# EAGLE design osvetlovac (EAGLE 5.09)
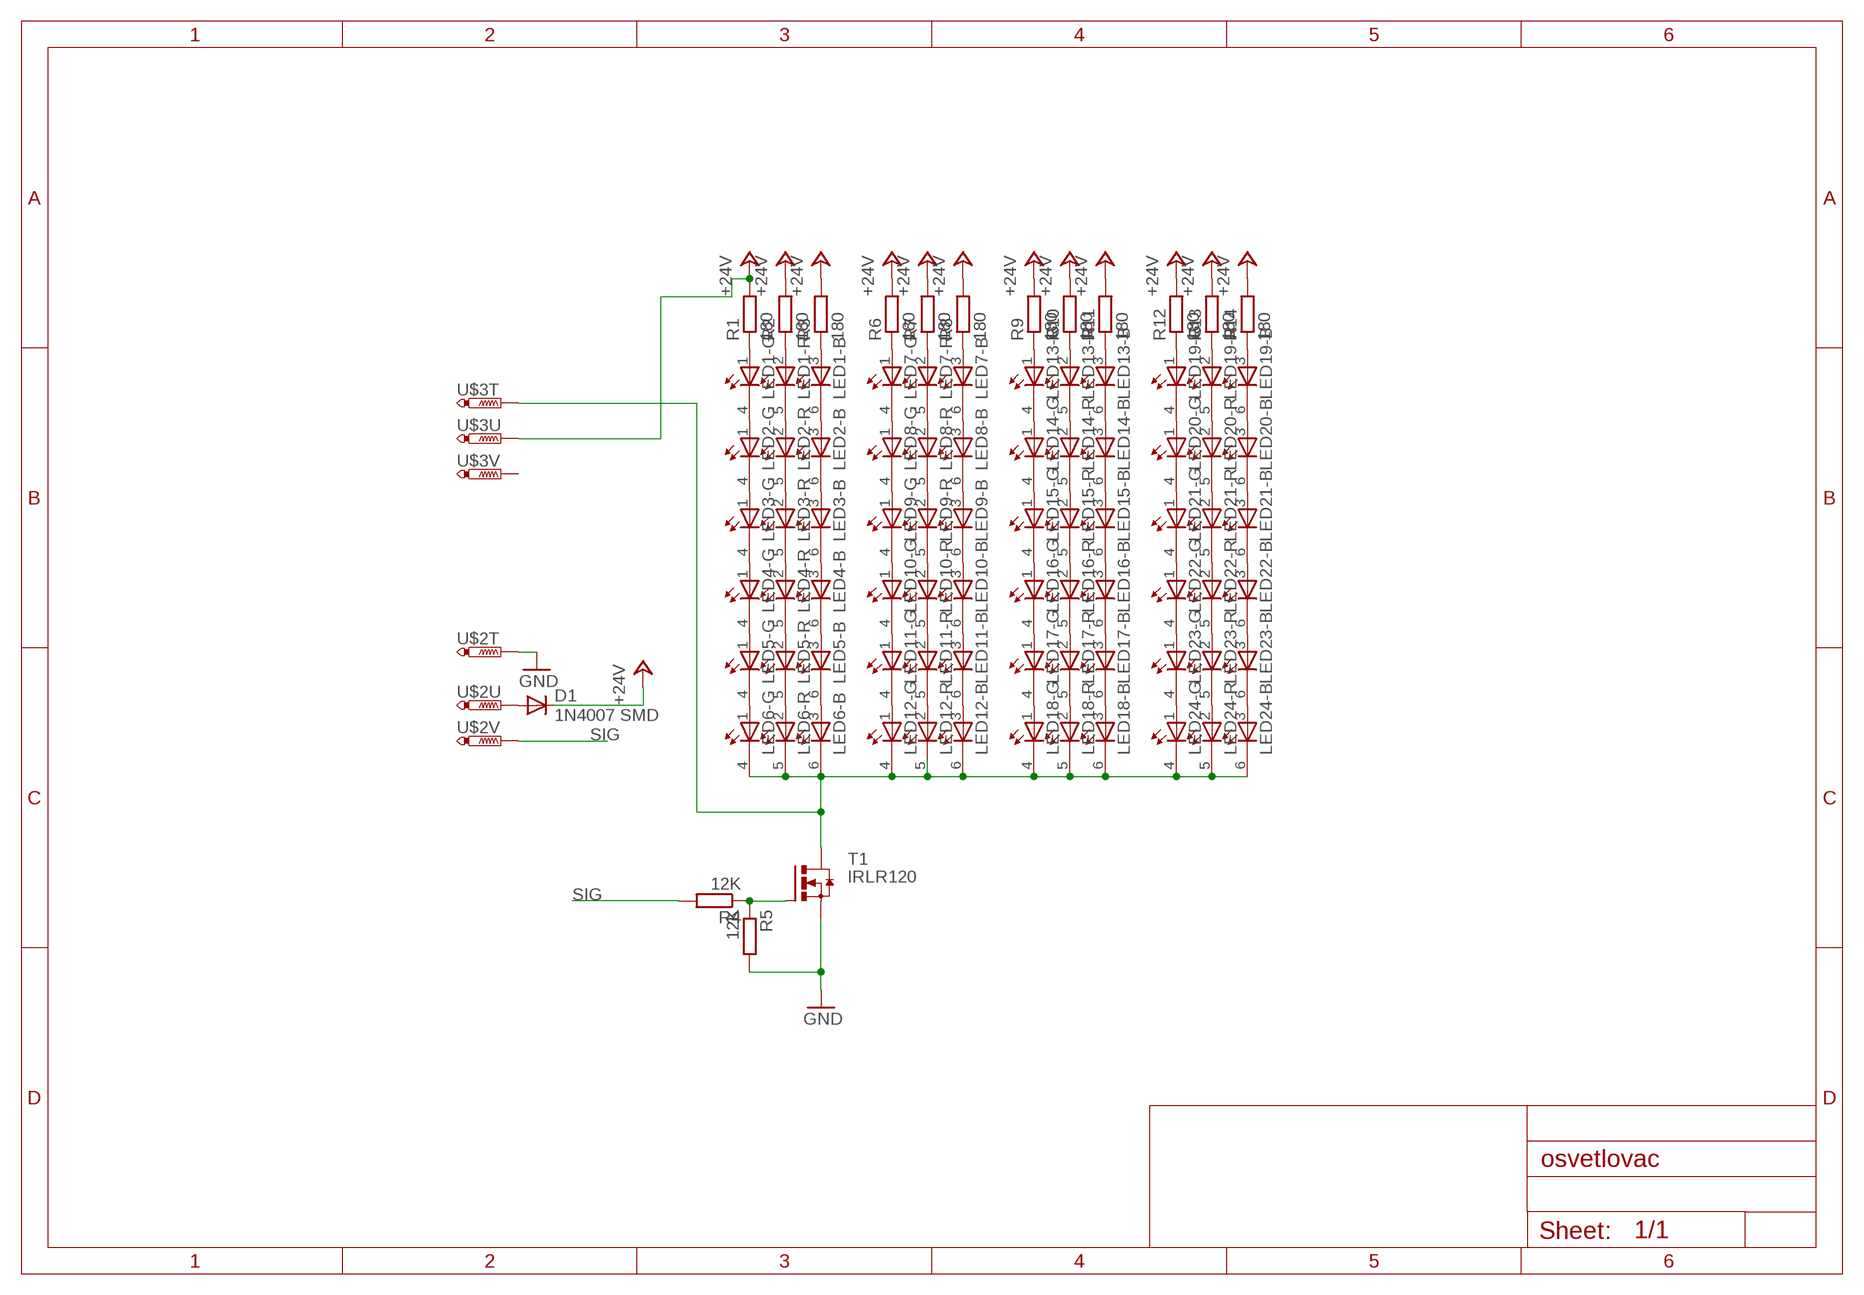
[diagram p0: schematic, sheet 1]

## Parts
D1  1N4007 SMD  DIODE-MELF-MLL41  [MELF-MLL41]
LED1  OVSTRGBBCR8  [OVSTRGBBCR8]
LED2  OVSTRGBBCR8  [OVSTRGBBCR8]
LED3  OVSTRGBBCR8  [OVSTRGBBCR8]
LED4  OVSTRGBBCR8  [OVSTRGBBCR8]
LED5  OVSTRGBBCR8  [OVSTRGBBCR8]
LED6  OVSTRGBBCR8  [OVSTRGBBCR8]
LED7  OVSTRGBBCR8  [OVSTRGBBCR8]
LED8  OVSTRGBBCR8  [OVSTRGBBCR8]
LED9  OVSTRGBBCR8  [OVSTRGBBCR8]
LED10  OVSTRGBBCR8  [OVSTRGBBCR8]
LED11  OVSTRGBBCR8  [OVSTRGBBCR8]
LED12  OVSTRGBBCR8  [OVSTRGBBCR8]
LED13  OVSTRGBBCR8  [OVSTRGBBCR8]
LED14  OVSTRGBBCR8  [OVSTRGBBCR8]
LED15  OVSTRGBBCR8  [OVSTRGBBCR8]
LED16  OVSTRGBBCR8  [OVSTRGBBCR8]
LED17  OVSTRGBBCR8  [OVSTRGBBCR8]
LED18  OVSTRGBBCR8  [OVSTRGBBCR8]
LED19  OVSTRGBBCR8  [OVSTRGBBCR8]
LED20  OVSTRGBBCR8  [OVSTRGBBCR8]
LED21  OVSTRGBBCR8  [OVSTRGBBCR8]
LED22  OVSTRGBBCR8  [OVSTRGBBCR8]
LED23  OVSTRGBBCR8  [OVSTRGBBCR8]
LED24  OVSTRGBBCR8  [OVSTRGBBCR8]
R1  180  R-EU_R0805  [R0805]
R2  180  R-EU_R0805  [R0805]
R3  180  R-EU_R0805  [R0805]
R4  12K  R-EU_R0805  [R0805]
R5  12K  R-EU_R0805  [R0805]
R6  180  R-EU_R0805  [R0805]
R7  180  R-EU_R0805  [R0805]
R8  180  R-EU_R0805  [R0805]
R9  180  R-EU_R0805  [R0805]
R10  180  R-EU_R0805  [R0805]
R11  180  R-EU_R0805  [R0805]
R12  180  R-EU_R0805  [R0805]
R13  180  R-EU_R0805  [R0805]
R14  180  R-EU_R0805  [R0805]
T1  IRLR120  [D-PAK_TO252AA]
U$2  3PIN  [PIN3]
U$3  3PIN  [PIN3]

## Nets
+24V: D1.C R1.2 R2.2 R3.2 R6.2 R7.2 R8.2 R9.2 R10.2 R11.2 R12.2 R13.2 R14.2 U$3.2
GND: R5.2 T1.3(S) U$2.1
N$1: LED1.4(-G:C) LED2.1(-G:A)
N$2: LED1.5(-R:C) LED2.2(-R:A)
N$3: LED1.6(-B:C) LED2.3(-B:A)
N$4: LED2.4(-G:C) LED3.1(-G:A)
N$5: LED2.5(-R:C) LED3.2(-R:A)
N$6: LED2.6(-B:C) LED3.3(-B:A)
N$7: LED3.4(-G:C) LED4.1(-G:A)
N$8: LED3.5(-R:C) LED4.2(-R:A)
N$9: LED3.6(-B:C) LED4.3(-B:A)
N$10: LED4.4(-G:C) LED5.1(-G:A)
N$11: LED4.5(-R:C) LED5.2(-R:A)
N$12: LED4.6(-B:C) LED5.3(-B:A)
N$13: LED5.4(-G:C) LED6.1(-G:A)
N$14: LED5.5(-R:C) LED6.2(-R:A)
N$15: LED5.6(-B:C) LED6.3(-B:A)
N$16: LED1.1(-G:A) R1.1
N$17: LED1.2(-R:A) R2.1
N$18: LED1.3(-B:A) R3.1
N$19: R4.1 R5.1 T1.1(G)
N$20: LED7.4(-G:C) LED8.1(-G:A)
N$21: LED7.5(-R:C) LED8.2(-R:A)
N$22: LED7.6(-B:C) LED8.3(-B:A)
N$23: LED8.4(-G:C) LED9.1(-G:A)
N$24: LED8.5(-R:C) LED9.2(-R:A)
N$25: LED8.6(-B:C) LED9.3(-B:A)
N$26: LED9.4(-G:C) LED10.1(-G:A)
N$27: LED9.5(-R:C) LED10.2(-R:A)
N$28: LED9.6(-B:C) LED10.3(-B:A)
N$29: LED10.4(-G:C) LED11.1(-G:A)
N$30: LED10.5(-R:C) LED11.2(-R:A)
N$31: LED10.6(-B:C) LED11.3(-B:A)
N$32: LED11.4(-G:C) LED12.1(-G:A)
N$33: LED11.5(-R:C) LED12.2(-R:A)
N$34: LED11.6(-B:C) LED12.3(-B:A)
N$35: LED7.1(-G:A) R6.1
N$36: LED7.2(-R:A) R7.1
N$37: LED7.3(-B:A) R8.1
N$38: LED13.4(-G:C) LED14.1(-G:A)
N$39: LED13.5(-R:C) LED14.2(-R:A)
N$40: LED13.6(-B:C) LED14.3(-B:A)
N$41: LED14.4(-G:C) LED15.1(-G:A)
N$42: LED14.5(-R:C) LED15.2(-R:A)
N$43: LED14.6(-B:C) LED15.3(-B:A)
N$44: LED15.4(-G:C) LED16.1(-G:A)
N$45: LED15.5(-R:C) LED16.2(-R:A)
N$46: LED15.6(-B:C) LED16.3(-B:A)
N$47: LED16.4(-G:C) LED17.1(-G:A)
N$48: LED16.5(-R:C) LED17.2(-R:A)
N$49: LED16.6(-B:C) LED17.3(-B:A)
N$50: LED17.4(-G:C) LED18.1(-G:A)
N$51: LED17.5(-R:C) LED18.2(-R:A)
N$52: LED17.6(-B:C) LED18.3(-B:A)
N$53: LED13.1(-G:A) R9.1
N$54: LED13.2(-R:A) R10.1
N$55: LED13.3(-B:A) R11.1
N$56: LED19.4(-G:C) LED20.1(-G:A)
N$57: LED19.5(-R:C) LED20.2(-R:A)
N$58: LED19.6(-B:C) LED20.3(-B:A)
N$59: LED20.4(-G:C) LED21.1(-G:A)
N$60: LED20.5(-R:C) LED21.2(-R:A)
N$61: LED20.6(-B:C) LED21.3(-B:A)
N$62: LED21.4(-G:C) LED22.1(-G:A)
N$63: LED21.5(-R:C) LED22.2(-R:A)
N$64: LED21.6(-B:C) LED22.3(-B:A)
N$65: LED22.4(-G:C) LED23.1(-G:A)
N$66: LED22.5(-R:C) LED23.2(-R:A)
N$67: LED22.6(-B:C) LED23.3(-B:A)
N$68: LED23.4(-G:C) LED24.1(-G:A)
N$69: LED23.5(-R:C) LED24.2(-R:A)
N$70: LED23.6(-B:C) LED24.3(-B:A)
N$71: LED19.1(-G:A) R12.1
N$72: LED19.2(-R:A) R13.1
N$73: LED19.3(-B:A) R14.1
N$74: LED6.4(-G:C) LED6.5(-R:C) LED6.6(-B:C) LED12.4(-G:C) LED12.5@1(-R:C) LED12.6(-B:C) LED18.4(-G:C) LED18.5(-R:C) LED18.6(-B:C) LED24.4(-G:C) LED24.5(-R:C) LED24.6(-B:C) T1.4(D) U$3.1
N$75: D1.A U$2.2
SIG: R4.2 U$2.3
Unconnected: LED1.4@1(-G:C) LED1.5@1(-R:C) LED1.6@1(-B:C) LED2.4@1(-G:C) LED2.5@1(-R:C) LED2.6@1(-B:C) LED3.4@1(-G:C) LED3.5@1(-R:C) LED3.6@1(-B:C) LED4.4@1(-G:C) LED4.5@1(-R:C) LED4.6@1(-B:C) LED5.4@1(-G:C) LED5.5@1(-R:C) LED5.6@1(-B:C) LED6.4@1(-G:C) LED6.5@1(-R:C) LED6.6@1(-B:C) LED7.4@1(-G:C) LED7.5@1(-R:C) LED7.6@1(-B:C) LED8.4@1(-G:C) LED8.5@1(-R:C) LED8.6@1(-B:C) LED9.4@1(-G:C) LED9.5@1(-R:C) LED9.6@1(-B:C) LED10.4@1(-G:C) LED10.5@1(-R:C) LED10.6@1(-B:C) LED11.4@1(-G:C) LED11.5@1(-R:C) LED11.6@1(-B:C) LED12.4@1(-G:C) LED12.5(-R:C) LED12.6@1(-B:C) LED13.4@1(-G:C) LED13.5@1(-R:C) LED13.6@1(-B:C) LED14.4@1(-G:C) LED14.5@1(-R:C) LED14.6@1(-B:C) LED15.4@1(-G:C) LED15.5@1(-R:C) LED15.6@1(-B:C) LED16.4@1(-G:C) LED16.5@1(-R:C) LED16.6@1(-B:C) LED17.4@1(-G:C) LED17.5@1(-R:C) LED17.6@1(-B:C) LED18.4@1(-G:C) LED18.5@1(-R:C) LED18.6@1(-B:C) LED19.4@1(-G:C) LED19.5@1(-R:C) LED19.6@1(-B:C) LED20.4@1(-G:C) LED20.5@1(-R:C) LED20.6@1(-B:C) LED21.4@1(-G:C) LED21.5@1(-R:C) LED21.6@1(-B:C) LED22.4@1(-G:C) LED22.5@1(-R:C) LED22.6@1(-B:C) LED23.4@1(-G:C) LED23.5@1(-R:C) LED23.6@1(-B:C) LED24.4@1(-G:C) LED24.5@1(-R:C) LED24.6@1(-B:C) U$3.3

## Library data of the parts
D1 = diode:DIODE-: DIODE
LED1-LED24 = led:OVSTRGBBCR8: Full Color PLCC6 LED OVSTRGBBCR8 Source: www.optekinc.com .. ovstrgbbcr8.pdf
R1-R14 = rcl:R-EU_: RESISTOR, European symbol
T1 = transistor-power:IRLR120
U$2 U$3 = testpad:3PIN

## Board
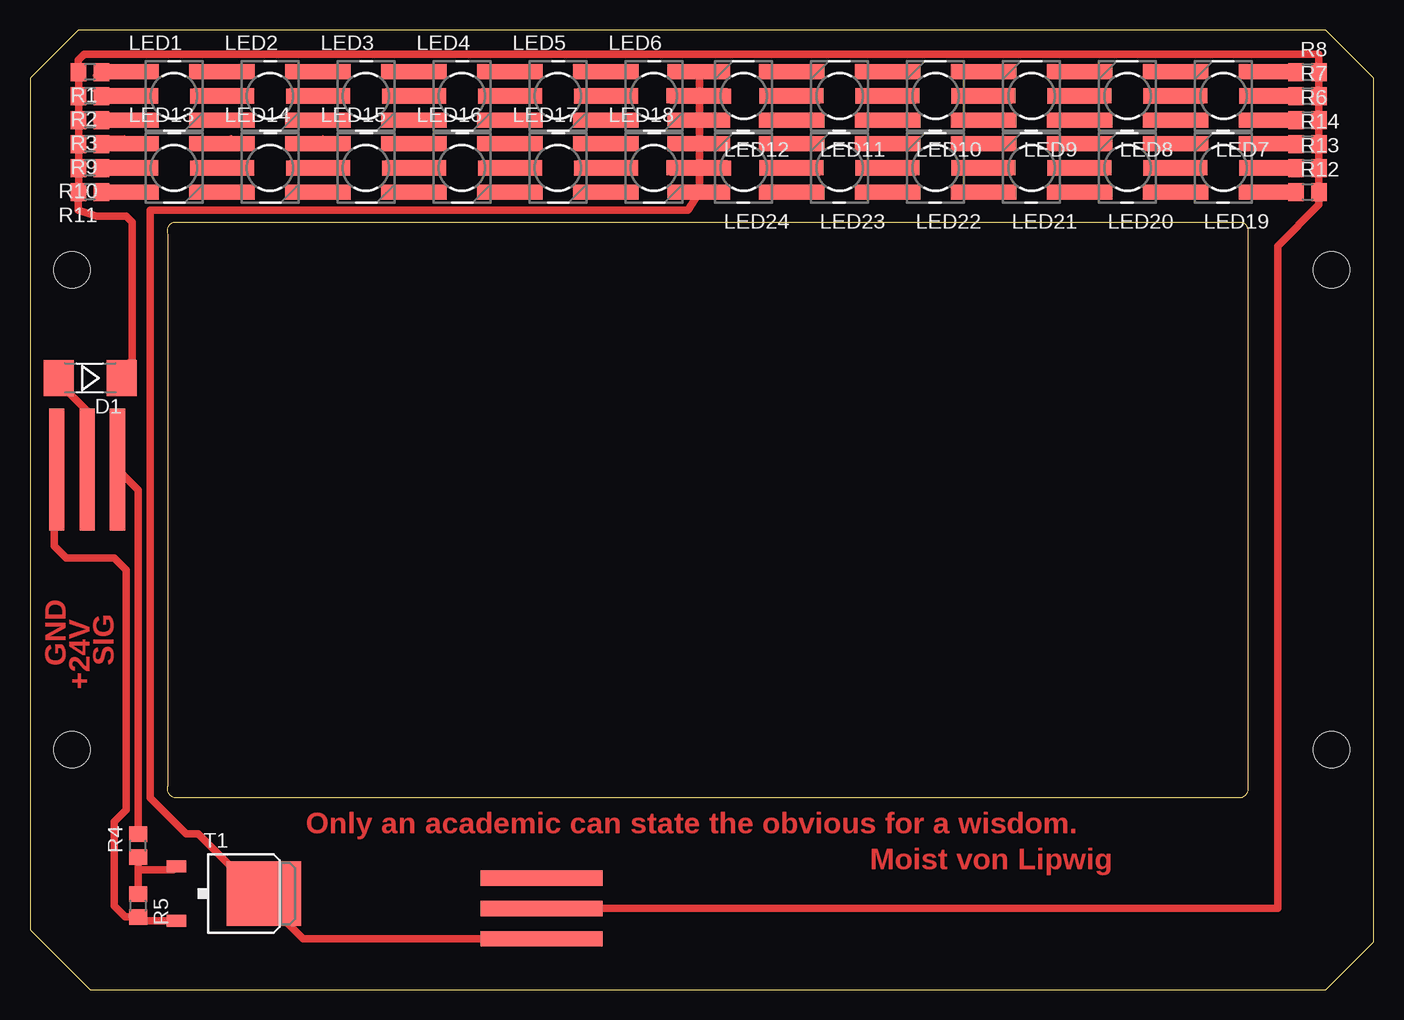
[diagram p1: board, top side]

Size 112 x 80 mm. Coordinates in mm from the lower left corner, seen from the top.
Outline: 108,0 112,4 112,76 108,80 4,80 0,76 0,5 5,0 108,0
Outline: 11.5,63 arc-90 12,64 101,64 arc-90 101.5,63 101.5,17 arc-90 101,16 12,16 arc-90 11.5,17 11.5,63
Copper layers (1*16): Top 0.035mm / dielectric 1.5mm / Bottom 0.035mm
Design rules "default": minimum track width 10mil, minimum drill 24mil, track to track 8mil, track to pad 8mil, pad to pad 8mil, via to via 8mil, smd to smd 8mil, copper to edge 40mil, drill to drill 8mil, minimum pad ring 10mil, minimum via ring 8mil, stop-mask expansion 4mil, vias tented up to drill 0mil, thermal gap 10mil
Holes 3 mm at 3.5,60 3.5,20 108.5,60 108.5,20

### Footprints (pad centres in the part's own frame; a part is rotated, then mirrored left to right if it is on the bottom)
MELF-MLL41 = smd 2.5 x 3: A 2.625,0; C -2.625,0
OVSTRGBBCR8 = smd 5.08 x 1.27: 1 -3.802,2.026; 2 -3.833,0; 3 -3.802,-2.026; 4 3.812,2.026; 5@1 3.91,-0.025; 6 3.812,-2.026 | smd 1.676 x 0.813: 4@1 3.322,1.936 | smd 1.422 x 0.711: 5 3.692,0 | smd 0.305 x 0.152: 6@1 3.002,-1.936
R0805 = smd 1.3 x 1.5: 1 -0.95,0; 2 0.95,0
D-PAK_TO252AA = smd 1 x 1.6: 1 -2.28,-4.8; 3 2.28,-4.8 | smd 5.4 x 6.2: 4 0,2.5
PIN3 = smd 1.27 x 10.16: 1 -17.78,6.35; 2 -15.24,6.35; 3 -12.7,6.35

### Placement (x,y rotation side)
D1  5,51 180 top
LED1  12,74.5 0 top
LED2  20,74.5 0 top
LED3  28,74.5 0 top
LED4  36,74.5 0 top
LED5  44,74.5 0 top
LED6  52,74.5 0 top
LED7  99.5,74.5 180 top
LED8  91.5,74.5 180 top
LED9  83.5,74.5 180 top
LED10  75.5,74.5 180 top
LED11  67.5,74.5 180 top
LED12  59.5,74.5 180 top
LED13  12,68.5 0 top
LED14  20,68.5 0 top
LED15  28,68.5 0 top
LED16  36,68.5 0 top
LED17  44,68.5 0 top
LED18  52,68.5 0 top
LED19  99.5,68.5 180 top
LED20  91.5,68.5 180 top
LED21  83.5,68.5 180 top
LED22  75.5,68.5 180 top
LED23  67.5,68.5 180 top
LED24  59.5,68.5 180 top
R1  5,76.5 180 top
R2  5,74.5 180 top
R3  5,72.5 180 top
R4  9,12 90 top
R5  9,7 270 top
R6  106.5,72.5 0 top
R7  106.5,74.5 0 top
R8  106.5,76.5 0 top
R9  5,70.5 180 top
R10  5,68.5 180 top
R11  5,66.5 180 top
R12  106.5,66.5 0 top
R13  106.5,68.5 0 top
R14  106.5,70.5 0 top
T1  17,8 270 top
U$2  20,37 0 top
U$3  49,22 90 top

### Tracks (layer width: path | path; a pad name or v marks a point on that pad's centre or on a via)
+24V
  Top 0.61: D1.C 7.55,51.55 8.5,52.5 8.5,64 8,64.5 5.5,64.5 4,65 4,66.45 R11.2 R10.2 R9.2 R3.2 R2.2 R1.2 4,76.55 4,77.5 4.5,78 107.45,78 107.45,76 | R14.2 R13.2 R12.2 107.45,65.45 104,62 104,6.76 U$3.2 | R14.2 | R14.2 R6.2 | R6.2 | R6.2 R7.2 | R7.2 | R7.2 107.45,76 | 107.45,76 R8.2
GND
  Top 0.61: U$2.1 2,43.13 2,37 3,36 7,36 8,35 8,15 7,14 7,7 7.95,6.05 R5.2 9.33,5.72 T1.3
N$1
  Top 0.254: LED1.4 16.78,76.2 LED2.1
N$2
  Top 0.61: LED2.2 LED1.5
N$3
  Top 0.254: LED2.3 16.78,72.39 LED1.6
N$4
  Top 0.61: LED3.1 LED2.4
N$5
  Top 0.61: LED3.2 LED2.5
N$6
  Top 0.254: LED3.3 24.4,72.39 LED2.6
N$7
  Top 0.61: LED4.1 LED3.4
N$8
  Top 0.61: LED4.2 LED3.5
N$9
  Top 0.254: LED3.6 32.02,72.39 LED4.3
N$10
  Top 0.61: LED5.1 LED4.4
N$11
  Top 0.61: LED5.2 LED4.5
N$12
  Top 0.61: LED4.6 LED5.3
N$13
  Top 0.61: LED6.1 LED5.4
N$14
  Top 0.61: LED6.2 LED5.5
N$15
  Top 0.61: LED5.6 LED6.3
N$16
  Top 0.254: R1.1 5.35,76.2 7.89,76.2 LED1.1
N$17
  Top 0.254: R2.1 5.35,74.93 7.89,74.93 LED1.2
N$18
  Top 0.254: R3.1 5.35,72.39 7.89,72.39 LED1.3
N$19
  Top 0.61: R5.1 9,10 | 9,10 R4.1 | T1.1 11.92,10 9,10
N$20
  Top 0.61: LED8.1 LED7.4
N$21
  Top 0.61: LED8.2 LED7.5
N$22
  Top 0.61: LED8.3 LED7.6 | LED7.6
N$23
  Top 0.61: LED9.1 LED8.4
N$24
  Top 0.61: LED9.2 LED8.5
N$25
  Top 0.61: LED9.3 | LED9.3 LED8.6
N$26
  Top 0.61: LED10.1 LED9.4
N$27
  Top 0.61: LED10.2 LED9.5
N$28
  Top 0.61: LED10.3 | LED10.3 LED9.6
N$29
  Top 0.61: LED11.1 LED10.4
N$30
  Top 0.61: LED11.2 LED10.5
N$31
  Top 0.61: LED11.3 | LED11.3 LED10.6
N$32
  Top 0.61: LED12.1 LED11.4
N$33
  Top 0.61: LED12.2 LED11.5
N$34
  Top 0.61: LED12.3 | LED12.3 LED11.6
N$35
  Top 0.61: R6.1 105.53,72.47 LED7.1
N$36
  Top 0.61: LED7.2 R7.1
N$37
  Top 0.61: R8.1 105.52,76.53 LED7.3
N$38
  Top 0.254: LED13.4 16.78,71.12 LED14.1
N$39
  Top 0.61: LED14.2 LED13.5
N$40
  Top 0.254: LED14.3 16.78,66.04 LED13.6
N$41
  Top 0.254: LED14.4 24.4,71.12 LED15.1
N$42
  Top 0.61: LED15.2 LED14.5
N$43
  Top 0.254: LED15.3 24.4,66.04 LED14.6
N$44
  Top 0.61: LED16.1 LED15.4
N$45
  Top 0.61: LED16.2 LED15.5
N$46
  Top 0.254: LED15.6 32.02,66.04 LED16.3
N$47
  Top 0.61: LED17.1 LED16.4
N$48
  Top 0.61: LED17.2 LED16.5
N$49
  Top 0.61: LED17.3 | LED17.3 LED16.6
N$50
  Top 0.61: LED18.1 LED17.4
N$51
  Top 0.61: LED18.2 LED17.5
N$52
  Top 0.61: LED18.3 | LED18.3 LED17.6
N$53
  Top 0.254: R9.1 5.35,71.12 7.89,71.12 LED13.1
N$54
  Top 0.254: R10.1 5.35,68.58 7.89,68.58 LED13.2
N$55
  Top 0.254: R11.1 5.35,66.04 7.89,66.04 LED13.3
N$56
  Top 0.61: LED20.1 LED19.4
N$57
  Top 0.61: LED20.2 LED19.5
N$58
  Top 0.61: LED20.3 LED19.6 | LED20.3
N$59
  Top 0.61: LED21.1 LED20.4
N$60
  Top 0.61: LED21.2 LED20.5
N$61
  Top 0.61: LED20.6 LED21.3
N$62
  Top 0.61: LED22.1 LED21.4
N$63
  Top 0.61: LED22.2 LED21.5
N$64
  Top 0.61: LED21.6 LED22.3
N$65
  Top 0.61: LED23.1 LED22.4
N$66
  Top 0.61: LED23.2 LED22.5
N$67
  Top 0.61: LED23.3 | LED23.3 LED22.6
N$68
  Top 0.61: LED24.1 LED23.4
N$69
  Top 0.61: LED24.2 LED23.5
N$70
  Top 0.61: LED23.6 LED24.3
N$71
  Top 0.61: R12.1 105.52,66.47 LED19.1
N$72
  Top 0.61: LED19.2 R13.1
N$73
  Top 0.61: R14.1 105.52,70.53 LED19.3
N$74
  Top 0.61: 19,8 T1.4 | 19,8 14,13 13,13 10,16 10,65 54.84,65 LED18.6 LED24.4 55.81,66.6 55.81,68.38 | LED18.4 LED6.6 | LED12.6 LED6.4 55.81,74.75 | 55.81,74.75 LED12.5@1 | 55.81,74.38 55.81,74.75 | LED6.6 LED12.4 | 55.81,68.38 LED18.4 | LED18.4 LED24.6 | 55.81,74.38 LED6.5 | LED6.6 55.81,74.38 | LED24.5 LED18.4 | 55.81,68.38 LED18.5 | U$3.1 22.78,4.22 19,8
N$75
  Top 0.61: D1.A 2.45,50.55 5,48 5,43.59 U$2.2
SIG
  Top 0.61: U$2.3 9,41.65 R4.2

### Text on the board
Top: GND | SIG | +24V | Only an academic can state the obvious for a wisdom. | Moist von Lipwig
